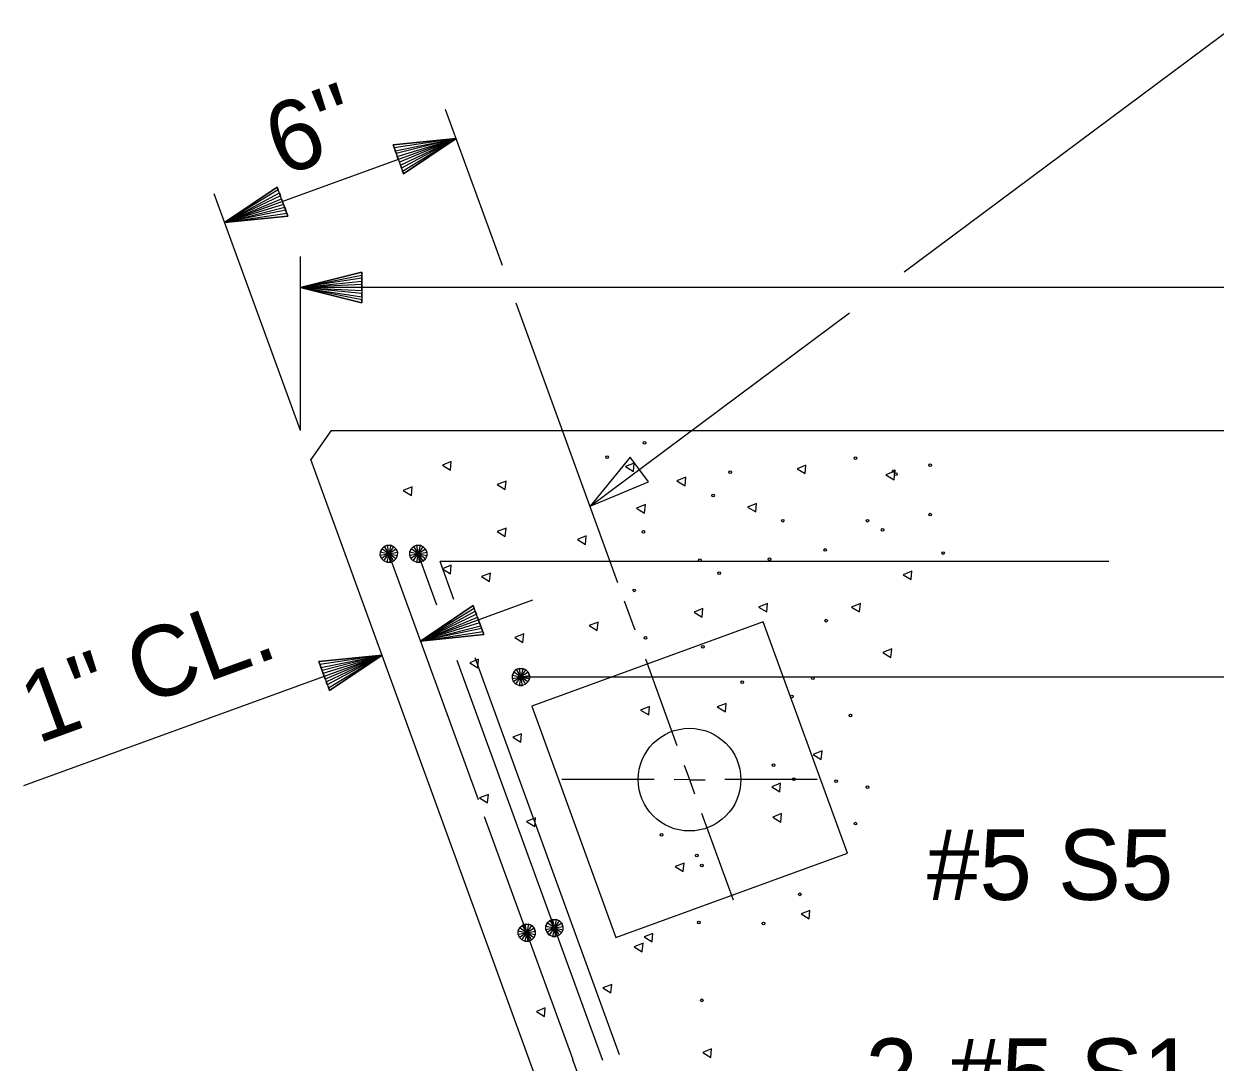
# Model space of a CAD drawing. Extents: x -408 to -23, y -15 to 117.
# Drawn here: x -113.161 to -110.743, y 61.962 to 64.069 of the extents above; entities that cross this region are included whole.
import ezdxf

# ---------------------------------------------------------------- set-up
doc = ezdxf.new("R2010")
doc.units = 0
for name, color, linetype in [('Arrowhead Terminators CELL', 7, 'Continuous'), ('Dimension Lines', 7, 'Continuous'), ('Rebar Lines', 7, 'Continuous'), ('Sup Concrete Girder Lines', 7, 'Continuous'), ('Sup Cored Slab Unit', 7, 'Continuous'), ('Text', 7, 'Continuous')]:
    doc.layers.add(name, color=color, linetype=linetype)

msp = doc.modelspace()

# ---------------------------------------------------------------- linework, layer by layer
at = {"layer": 'Arrowhead Terminators CELL'}
msp.add_lwpolyline([(-112.012, 63.0903), (-111.8931, 63.1399), (-111.9305, 63.19)], close=True, dxfattribs=at)
at = {"layer": 'Dimension Lines'}
for p, q in [((-112.1898, 63.5788), (-112.3051, 63.8955)), ((-112.2837, 63.8367), (-112.7535, 63.6657)), ((-112.6, 63.2438), (-112.7749, 63.7245)), ((-112.6, 63.2438), (-112.6, 63.5968)), ((-108.8081, 63.5343), (-112.6, 63.5343)), ((-111.9554, 62.9348), (-112.1619, 63.5022)), ((-112.1286, 62.8996), (-112.3559, 62.8168)), ((-111.9206, 62.839), (-111.942, 62.8977)), ((-113.1612, 62.5236), (-112.4342, 62.7883)), ((-111.835, 62.6041), (-111.8991, 62.7802)), ((-111.8816, 62.5355), (-112.0691, 62.5355)), ((-111.5509, 62.5355), (-111.7384, 62.5355)), ((-111.7209, 62.2907), (-111.7851, 62.4668))]:
    msp.add_line(p, q, dxfattribs=at)
for points in [[(-111.3742, 63.5657), (-110.6987, 64.0691), (-110.1398, 64.0691)], [(-112.4012, 63.794), (-112.4034, 63.7999), (-112.2837, 63.8367), (-112.4055, 63.8058), (-112.4076, 63.8116), (-112.2837, 63.8367), (-112.4097, 63.8175), (-112.4119, 63.8234), (-112.2837, 63.8367), (-112.3906, 63.7646), (-112.3926, 63.7705), (-112.2837, 63.8367), (-112.3947, 63.7764), (-112.3969, 63.7822), (-112.2837, 63.8367), (-112.399, 63.7882), (-112.4119, 63.8234), (-112.3906, 63.7646), (-112.2837, 63.8367), (-112.4119, 63.8234)], [(-112.6362, 63.7085), (-112.634, 63.7026), (-112.7536, 63.6657), (-112.6318, 63.6968), (-112.6297, 63.6909), (-112.7536, 63.6657), (-112.6276, 63.685), (-112.6254, 63.6791), (-112.7536, 63.6657), (-112.6468, 63.7378), (-112.6447, 63.732), (-112.7536, 63.6657), (-112.6425, 63.7261), (-112.6404, 63.7202), (-112.7536, 63.6657), (-112.6383, 63.7143), (-112.6254, 63.6791), (-112.6468, 63.7378), (-112.7536, 63.6657), (-112.6254, 63.6791)], [(-112.475, 63.5343), (-112.475, 63.5405), (-112.6, 63.5343), (-112.475, 63.5468), (-112.475, 63.553), (-112.6, 63.5343), (-112.475, 63.5593), (-112.475, 63.5655), (-112.6, 63.5343), (-112.475, 63.503), (-112.475, 63.5093), (-112.6, 63.5343), (-112.475, 63.5155), (-112.475, 63.5218), (-112.6, 63.5343), (-112.475, 63.528), (-112.475, 63.5655), (-112.475, 63.503), (-112.6, 63.5343), (-112.475, 63.5655)], [(-112.012, 63.0903), (-111.4856, 63.4827)], [(-112.2385, 62.8595), (-112.2364, 62.8537), (-112.3559, 62.8168), (-112.2342, 62.8478), (-112.232, 62.8419), (-112.3559, 62.8168), (-112.2299, 62.8361), (-112.2278, 62.8302), (-112.3559, 62.8168), (-112.2492, 62.8889), (-112.247, 62.883), (-112.3559, 62.8168), (-112.2449, 62.8771), (-112.2427, 62.8712), (-112.3559, 62.8168), (-112.2406, 62.8654), (-112.2278, 62.8302), (-112.2492, 62.8889), (-112.3559, 62.8168), (-112.2278, 62.8302)], [(-112.5517, 62.7455), (-112.5539, 62.7513), (-112.4342, 62.7883), (-112.556, 62.7573), (-112.5582, 62.7632), (-112.4342, 62.7883), (-112.5603, 62.7691), (-112.5623, 62.7749), (-112.4342, 62.7883), (-112.541, 62.7162), (-112.5431, 62.7221), (-112.4342, 62.7883), (-112.5453, 62.728), (-112.5473, 62.7338), (-112.4342, 62.7883), (-112.5496, 62.7396), (-112.5623, 62.7749), (-112.541, 62.7162), (-112.4342, 62.7883), (-112.5623, 62.7749)], [(-111.8208, 62.5649), (-111.81, 62.5355), (-111.8416, 62.5353)], [(-111.799, 62.5058), (-111.8097, 62.5352), (-111.7783, 62.5353)]]:
    msp.add_lwpolyline(points, dxfattribs=at)
at = {"layer": 'Rebar Lines'}
for p, q in [((-112.2385, 62.4942), (-112.4203, 62.9938)), ((-112.3227, 62.8895), (-112.3606, 62.9938)), ((-110.959, 62.9782), (-112.3163, 62.9782)), ((-112.2882, 62.9009), (-112.3163, 62.9782)), ((-111.9862, 61.9653), (-112.2817, 62.777)), ((-111.9521, 61.9774), (-112.2452, 62.7826)), ((-112.1524, 62.7438), (-109.4649, 62.7438)), ((-112.0466, 61.9669), (-112.2262, 62.4603)), ((-111.7438, 61.1348), (-112.0467, 61.9669))]:
    msp.add_line(p, q, dxfattribs=at)
for points in [[(-112.4377, 62.9908), (-112.4376, 62.9976), (-112.4348, 63.0039), (-112.4298, 63.0087), (-112.4234, 63.0111), (-112.4165, 63.011), (-112.4102, 63.0082), (-112.4055, 63.0033), (-112.403, 62.9969), (-112.4032, 62.99), (-112.4059, 62.9837), (-112.4109, 62.9789), (-112.4173, 62.9764), (-112.4242, 62.9766), (-112.4304, 62.9794), (-112.4352, 62.9843), (-112.4377, 62.9908), (-112.4203, 62.9938), (-112.403, 62.9969), (-112.4055, 63.0033), (-112.4203, 62.9938), (-112.4102, 63.0082), (-112.4165, 63.011), (-112.4203, 62.9938), (-112.4234, 63.0111), (-112.4298, 63.0087), (-112.4203, 62.9938), (-112.4348, 63.0039), (-112.4376, 62.9976), (-112.4203, 62.9938), (-112.4352, 62.9843), (-112.4304, 62.9794), (-112.4203, 62.9938), (-112.4242, 62.9766), (-112.4173, 62.9764), (-112.4203, 62.9938), (-112.4109, 62.9789), (-112.4059, 62.9837), (-112.4203, 62.9938), (-112.4032, 62.99)], [(-112.3779, 62.9907), (-112.3778, 62.9975), (-112.3751, 63.0038), (-112.3701, 63.0086), (-112.3636, 63.0111), (-112.3568, 63.011), (-112.3505, 63.0082), (-112.3458, 63.0033), (-112.3433, 62.9968), (-112.3434, 62.99), (-112.3462, 62.9837), (-112.3511, 62.9789), (-112.3575, 62.9764), (-112.3644, 62.9765), (-112.3707, 62.9793), (-112.3754, 62.9843), (-112.3779, 62.9907), (-112.3606, 62.9938), (-112.3433, 62.9968), (-112.3458, 63.0033), (-112.3606, 62.9938), (-112.3505, 63.0082), (-112.3568, 63.011), (-112.3606, 62.9938), (-112.3636, 63.0111), (-112.3701, 63.0086), (-112.3606, 62.9938), (-112.3751, 63.0038), (-112.3778, 62.9975), (-112.3606, 62.9938), (-112.3754, 62.9843), (-112.3707, 62.9793), (-112.3606, 62.9938), (-112.3644, 62.9765), (-112.3575, 62.9764), (-112.3606, 62.9938), (-112.3511, 62.9789), (-112.3462, 62.9837), (-112.3606, 62.9938), (-112.3434, 62.99)], [(-112.1697, 62.7407), (-112.1696, 62.7476), (-112.1668, 62.7539), (-112.1619, 62.7587), (-112.1554, 62.7611), (-112.1486, 62.761), (-112.1423, 62.7582), (-112.1375, 62.7533), (-112.135, 62.7469), (-112.1352, 62.74), (-112.138, 62.7337), (-112.1429, 62.7289), (-112.1493, 62.7264), (-112.1562, 62.7265), (-112.1624, 62.7293), (-112.1672, 62.7343), (-112.1697, 62.7407), (-112.1524, 62.7438), (-112.135, 62.7469), (-112.1375, 62.7533), (-112.1524, 62.7438), (-112.1423, 62.7582), (-112.1486, 62.761), (-112.1524, 62.7438), (-112.1554, 62.7611), (-112.1619, 62.7587), (-112.1524, 62.7438), (-112.1668, 62.7539), (-112.1696, 62.7476), (-112.1524, 62.7438), (-112.1672, 62.7343), (-112.1624, 62.7293), (-112.1524, 62.7438), (-112.1562, 62.7265), (-112.1493, 62.7264), (-112.1524, 62.7438), (-112.1429, 62.7289), (-112.138, 62.7337), (-112.1524, 62.7438), (-112.1352, 62.74)], [(-112.1578, 62.2218), (-112.1577, 62.2286), (-112.1549, 62.2349), (-112.15, 62.2397), (-112.1435, 62.2421), (-112.1367, 62.242), (-112.1304, 62.2392), (-112.1257, 62.2343), (-112.1232, 62.2278), (-112.1233, 62.221), (-112.1261, 62.2147), (-112.131, 62.2099), (-112.1374, 62.2074), (-112.1443, 62.2076), (-112.1506, 62.2103), (-112.1553, 62.2153), (-112.1578, 62.2218), (-112.1405, 62.2248), (-112.1232, 62.2278), (-112.1257, 62.2343), (-112.1405, 62.2248), (-112.1304, 62.2392), (-112.1367, 62.242), (-112.1405, 62.2248), (-112.1435, 62.2421), (-112.15, 62.2397), (-112.1405, 62.2248), (-112.1549, 62.2349), (-112.1577, 62.2286), (-112.1405, 62.2248), (-112.1553, 62.2153), (-112.1506, 62.2103), (-112.1405, 62.2248), (-112.1443, 62.2076), (-112.1374, 62.2074), (-112.1405, 62.2248), (-112.131, 62.2099), (-112.1261, 62.2147), (-112.1405, 62.2248), (-112.1233, 62.221)], [(-112.1016, 62.2316), (-112.1015, 62.2385), (-112.0988, 62.2448), (-112.0938, 62.2496), (-112.0874, 62.252), (-112.0806, 62.2519), (-112.0742, 62.2491), (-112.0695, 62.2442), (-112.067, 62.2377), (-112.0672, 62.2309), (-112.0699, 62.2246), (-112.0748, 62.2198), (-112.0812, 62.2173), (-112.0882, 62.2175), (-112.0944, 62.2202), (-112.0992, 62.2252), (-112.1016, 62.2316), (-112.0843, 62.2347), (-112.067, 62.2377), (-112.0695, 62.2442), (-112.0843, 62.2347), (-112.0742, 62.2491), (-112.0806, 62.2519), (-112.0843, 62.2347), (-112.0874, 62.252), (-112.0938, 62.2496), (-112.0843, 62.2347), (-112.0988, 62.2448), (-112.1015, 62.2385), (-112.0843, 62.2347), (-112.0992, 62.2252), (-112.0944, 62.2202), (-112.0843, 62.2347), (-112.0882, 62.2175), (-112.0812, 62.2173), (-112.0843, 62.2347), (-112.0748, 62.2198), (-112.0699, 62.2246), (-112.0843, 62.2347), (-112.0672, 62.2309)]]:
    msp.add_lwpolyline(points, dxfattribs=at)
at = {"layer": 'Sup Concrete Girder Lines'}
for p, q in [((-112.5375, 63.2438), (-112.5787, 63.185)), ((-112.5375, 63.2438), (-107.0147, 63.2438)), ((-111.5081, 60.2438), (-112.5787, 63.185))]:
    msp.add_line(p, q, dxfattribs=at)
for points in [[(-112.2952, 63.1637), (-112.2938, 63.181), (-112.3117, 63.1738), (-112.2952, 63.1637)], [(-111.9237, 63.1605), (-111.9223, 63.1777), (-111.9402, 63.1706), (-111.9237, 63.1605)], [(-111.5754, 63.1564), (-111.5739, 63.1737), (-111.5919, 63.1665), (-111.5754, 63.1564)], [(-111.3951, 63.1441), (-111.3936, 63.1614), (-111.4116, 63.1543), (-111.3951, 63.1441)], [(-112.184, 63.124), (-112.1825, 63.1412), (-112.2005, 63.1341), (-112.184, 63.124)], [(-111.8192, 63.1318), (-111.8178, 63.149), (-111.8358, 63.1419), (-111.8192, 63.1318)], [(-112.3747, 63.1121), (-112.3733, 63.1294), (-112.3912, 63.1222), (-112.3747, 63.1121)], [(-111.9012, 63.0765), (-111.8997, 63.0937), (-111.9177, 63.0866), (-111.9012, 63.0765)], [(-111.6758, 63.0786), (-111.6744, 63.0958), (-111.6923, 63.0887), (-111.6758, 63.0786)], [(-112.184, 63.0287), (-112.1825, 63.0459), (-112.2005, 63.0388), (-112.184, 63.0287)], [(-112.0211, 63.0127), (-112.0196, 63.03), (-112.0376, 63.0228), (-112.0211, 63.0127)], [(-112.2952, 62.9532), (-112.2938, 62.9704), (-112.3117, 62.9633), (-112.2952, 62.9532)], [(-112.2158, 62.9373), (-112.2143, 62.9545), (-112.2323, 62.9474), (-112.2158, 62.9373)], [(-111.3603, 62.9413), (-111.3588, 62.9585), (-111.3768, 62.9514), (-111.3603, 62.9413)], [(-111.6533, 62.8757), (-111.6518, 62.893), (-111.6698, 62.8858), (-111.6533, 62.8757)], [(-111.4648, 62.8757), (-111.4633, 62.893), (-111.4813, 62.8858), (-111.4648, 62.8757)], [(-111.7844, 62.8655), (-111.7829, 62.8827), (-111.8009, 62.8756), (-111.7844, 62.8655)], [(-111.9973, 62.838), (-111.9958, 62.8552), (-112.0138, 62.8481), (-111.9973, 62.838)], [(-112.1482, 62.8141), (-112.1467, 62.8313), (-112.1647, 62.8242), (-112.1482, 62.8141)], [(-111.4012, 62.7835), (-111.3998, 62.8008), (-111.4177, 62.7936), (-111.4012, 62.7835)], [(-112.2396, 62.7625), (-112.2382, 62.7797), (-112.2561, 62.7726), (-112.2396, 62.7625)], [(-111.893, 62.6667), (-111.8915, 62.6839), (-111.9095, 62.6768), (-111.893, 62.6667)], [(-111.7373, 62.6728), (-111.7358, 62.6901), (-111.7538, 62.683), (-111.7373, 62.6728)], [(-112.1522, 62.6115), (-112.1508, 62.6287), (-112.1687, 62.6216), (-112.1522, 62.6115)], [(-111.5426, 62.5765), (-111.5412, 62.5938), (-111.5591, 62.5866), (-111.5426, 62.5765)], [(-111.6266, 62.511), (-111.6252, 62.5282), (-111.6432, 62.5211), (-111.6266, 62.511)], [(-112.2198, 62.4883), (-112.2183, 62.5056), (-112.2363, 62.4984), (-112.2198, 62.4883)], [(-112.1244, 62.4407), (-112.1229, 62.4579), (-112.1409, 62.4508), (-112.1244, 62.4407)], [(-111.6246, 62.4495), (-111.6231, 62.4668), (-111.6411, 62.4596), (-111.6246, 62.4495)], [(-111.8228, 62.3491), (-111.8213, 62.3663), (-111.8393, 62.3592), (-111.8228, 62.3491)], [(-111.5672, 62.2528), (-111.5658, 62.2701), (-111.5837, 62.263), (-111.5672, 62.2528)], [(-111.886, 62.2062), (-111.8846, 62.2235), (-111.9025, 62.2163), (-111.886, 62.2062)], [(-111.9059, 62.1863), (-111.9044, 62.2036), (-111.9224, 62.1964), (-111.9059, 62.1863)], [(-111.9695, 62.1029), (-111.968, 62.1201), (-111.986, 62.113), (-111.9695, 62.1029)], [(-112.1045, 62.0552), (-112.1031, 62.0725), (-112.121, 62.0653), (-112.1045, 62.0552)], [(-111.7668, 61.9718), (-111.7653, 61.989), (-111.7833, 61.9819), (-111.7668, 61.9718)]]:
    msp.add_lwpolyline(points, dxfattribs=at)
for centre, radius in [((-111.9017, 63.2187), 0.00273), ((-111.9775, 63.19), 0.00273), ((-111.4735, 63.1879), 0.00273), ((-111.7276, 63.1593), 0.00273), ((-111.3957, 63.1613), 0.00273), ((-111.3915, 63.1552), 0.00273), ((-111.3219, 63.1736), 0.00273), ((-111.7624, 63.1122), 0.00273), ((-111.621, 63.0609), 0.00273), ((-111.4489, 63.0609), 0.00273), ((-111.3219, 63.0732), 0.00273), ((-111.9038, 63.0384), 0.00273), ((-111.4182, 63.0425), 0.00273), ((-111.535, 63.0015), 0.00273), ((-111.2952, 62.9953), 0.00273), ((-111.789, 62.981), 0.00273), ((-111.6477, 62.983), 0.00273), ((-111.7501, 62.9544), 0.00273), ((-111.9222, 62.9196), 0.00273), ((-111.5329, 62.8581), 0.00273), ((-111.8997, 62.8232), 0.00273), ((-111.7829, 62.8048), 0.00273), ((-111.703, 62.7331), 0.00273), ((-111.5596, 62.7413), 0.00273), ((-111.6026, 62.7044), 0.00273), ((-111.4837, 62.6655), 0.00273), ((-111.81, 62.5355), 0.1042), ((-111.6395, 62.5651), 0.00273), ((-111.5985, 62.5364), 0.00273), ((-111.5124, 62.5323), 0.00273), ((-111.4489, 62.52), 0.00273), ((-111.4735, 62.4462), 0.00273), ((-111.8669, 62.4237), 0.00273), ((-111.7955, 62.3817), 0.00273), ((-111.7852, 62.3612), 0.00273), ((-111.5862, 62.3028), 0.00273), ((-111.7911, 62.2454), 0.00273), ((-111.66, 62.2434), 0.00273), ((-111.7849, 62.0877), 0.00273)]:
    msp.add_circle(centre, radius, dxfattribs=at)
at = {"layer": 'Sup Cored Slab Unit'}
msp.add_lwpolyline([(-111.6606, 62.8559), (-112.1304, 62.6849), (-111.9594, 62.215), (-111.4896, 62.386)], close=True, dxfattribs=at)

# ---------------------------------------------------------------- texts
at = {"layer": 'Text'}
for s, rotation, p in [("6''", 19.9877, (-112.6376, 63.7581)), ('1" CL.', 20.0021, (-113.1336, 62.6075))]:
    msp.add_text(s, height=0.14302, rotation=rotation, dxfattribs=at).set_placement(p)
for s, p in [('#5 S5', (-111.328, 62.2915)), ('2-#5 S1', (-111.4532, 61.8673))]:
    msp.add_text(s, height=0.14302, dxfattribs=at).set_placement(p)

doc.saveas('drawing.dxf')
